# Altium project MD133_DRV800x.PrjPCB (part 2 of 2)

## Sheet MD133_TCAN284x.SchDoc: TCAN284x-Q1
size 431 x 279 mm; Date: Not shown in title block; ApprovedBy: Not shown in title block; CheckedBy: Not shown in title block; Author: Not shown in title block; CompanyName: Not shown in title block; DrawnBy: Mojtaba Afshar; Engineer: Not shown in title block; Organization: Not shown in title block; Address1: Not shown in title block; Address2: Not shown in title block; Address3: Not shown in title block; Address4: Not shown in title block; DocumentNumber: 1; Revision: Use project parameter SCH_Rev; SheetNumber: 5; SheetTotal: 1; PageSetup: Record=PageOptions¦CenterHorizontal=True¦CenterVertical=True¦PrintScale=1.00¦XCorrection=1.00¦YCorrection=1.00¦PrintKind=0¦BorderSize=5000000¦LeftOffset=0¦BottomOffset=0¦Orientation=2¦PaperLength=1000¦PaperWidth=1000¦Scale=100¦PaperSource=15¦PrintQuality=600¦MediaType=1¦DitherType=10¦PaperKind=Letter¦PrintScaleMode=1
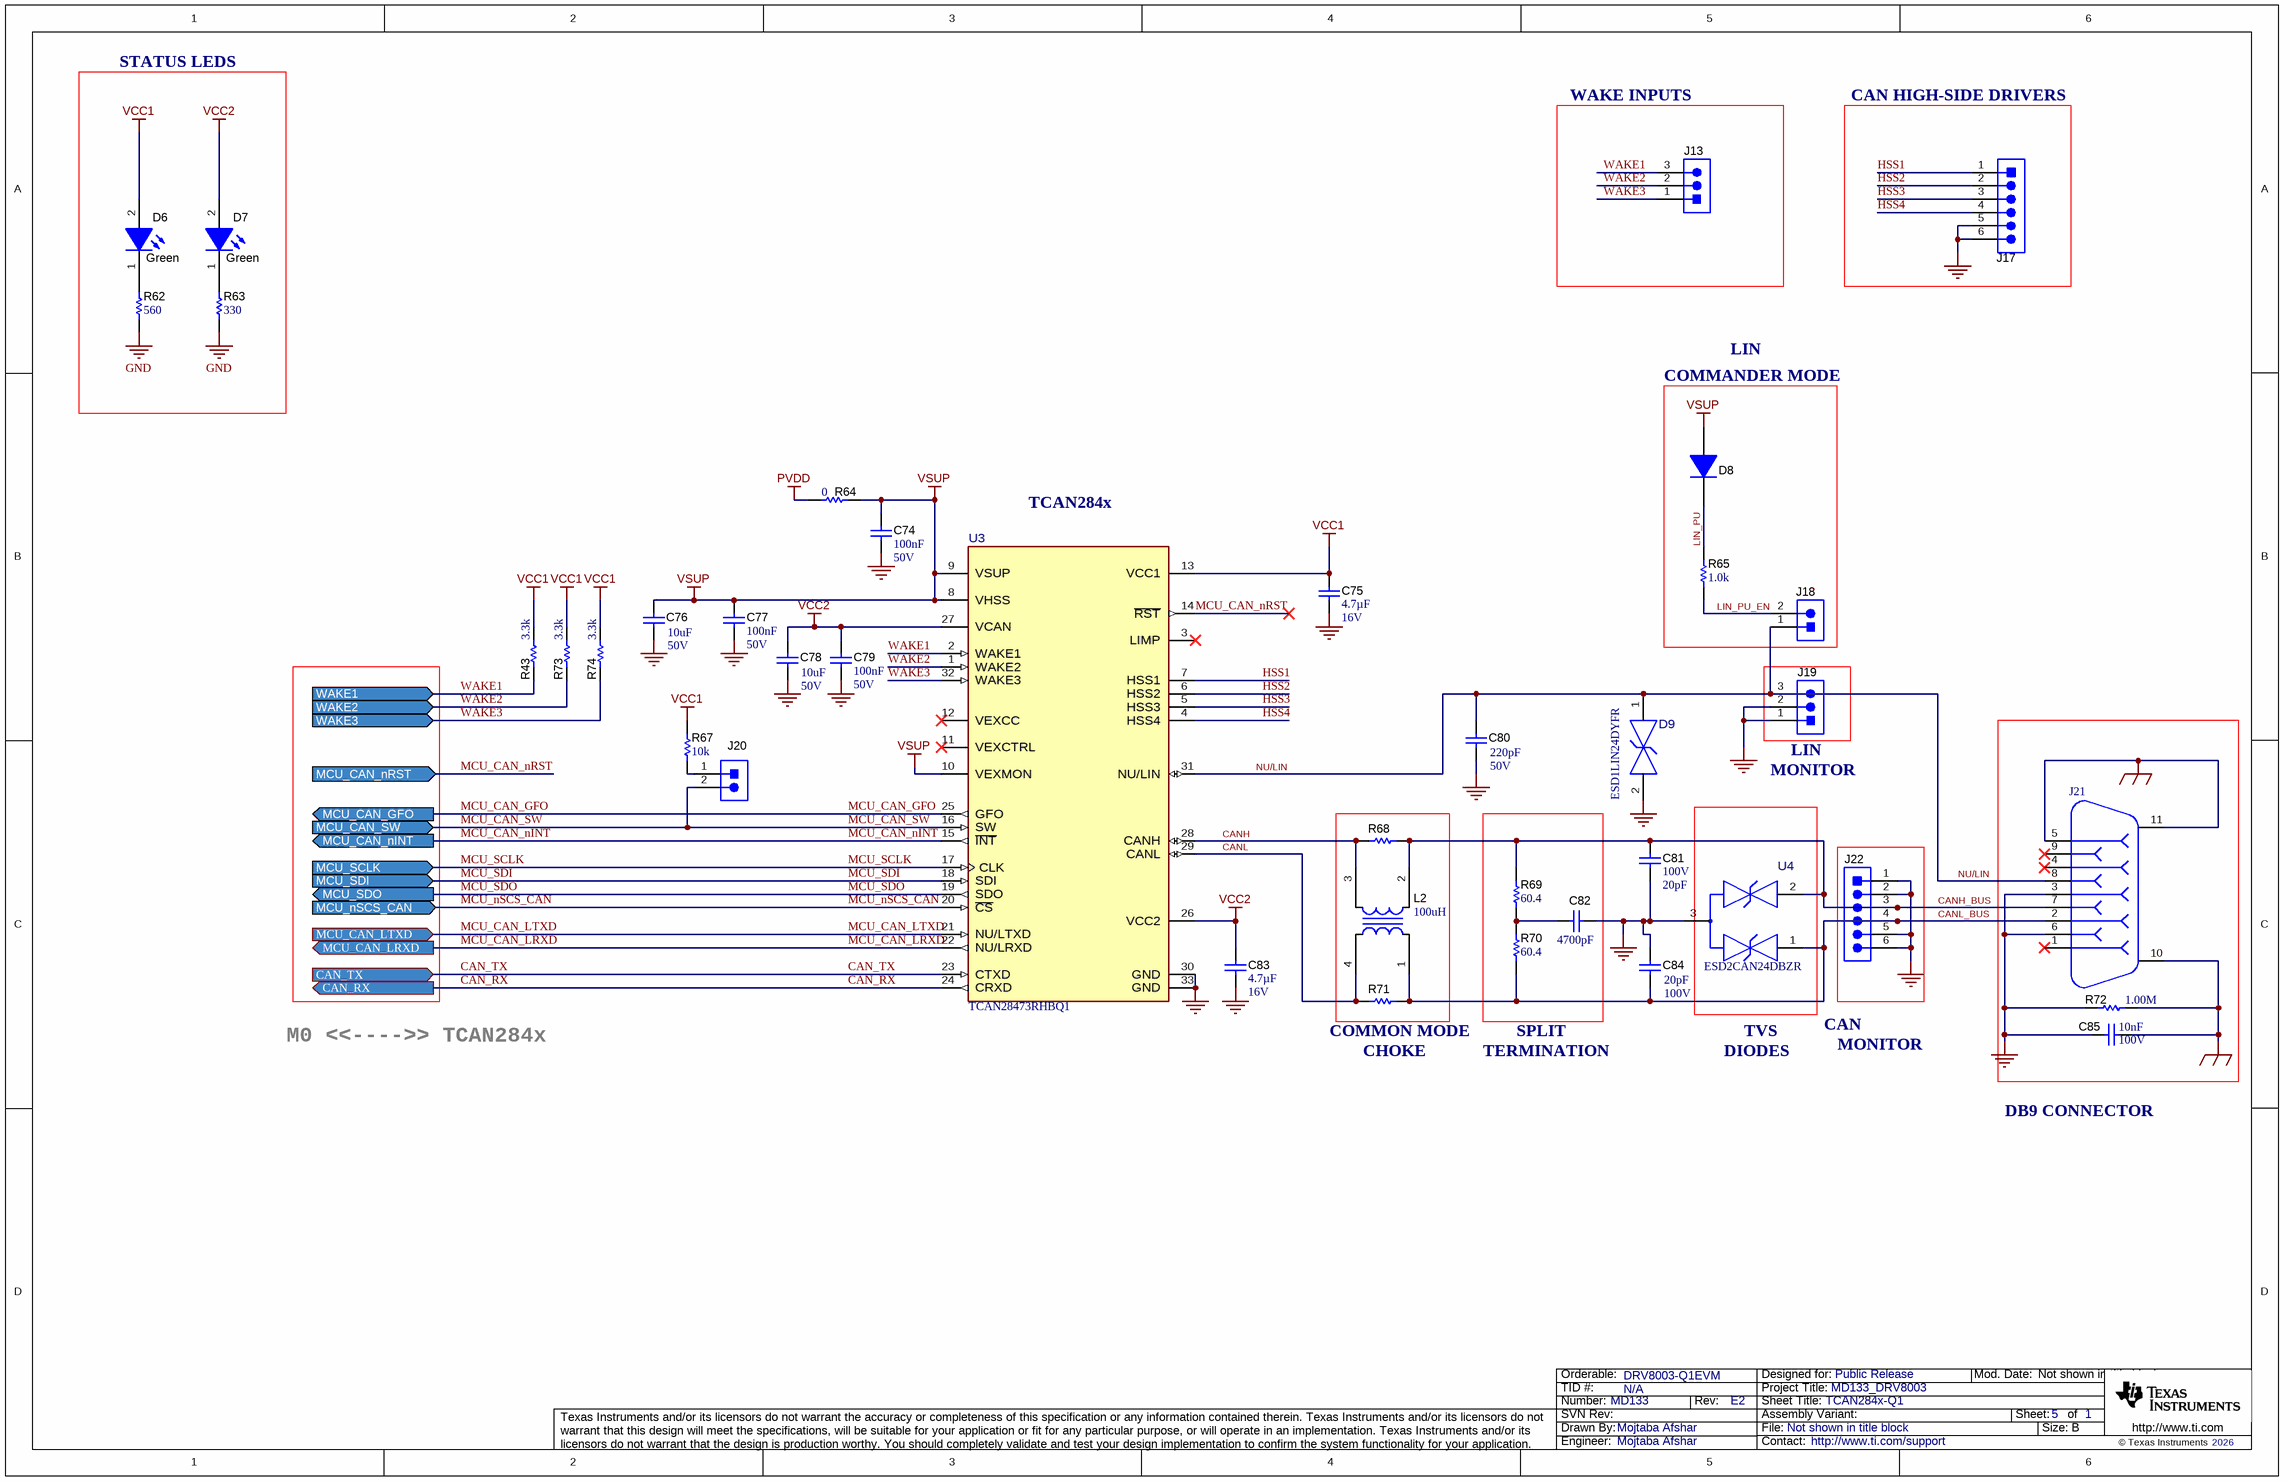
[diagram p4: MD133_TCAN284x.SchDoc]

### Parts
C74  Cap_F: 100nF  VDC_V: 50V  [0603S]  (hidden comment: C1608X7R1H104K080AA)
C75  Cap_F: 4.7µF  VDC_V: 16V  [0805L]  (hidden comment: CGA4J3X7R1C475K125AE)
C76  VDC_V: 50V  ValueDisplayed: 10uF  [1206_180]  (hidden comment: CL31B106KBHNNNE)
C77  Cap_F: 100nF  VDC_V: 50V  [0603S]  (hidden comment: C1608X7R1H104K080AA)
C78  VDC_V: 50V  ValueDisplayed: 10uF  [1206_180]  (hidden comment: CL31B106KBHNNNE)
C79  Cap_F: 100nF  VDC_V: 50V  [0603S]  (hidden comment: C1608X7R1H104K080AA)
C80  Value2: 50V  ValueDisplayed: 220pF  [0603S]  (hidden comment: 06035A221FAT2A)
C81  VDC_V: 100V  ValueDisplayed: 20pF  [0603S]  (hidden comment: GRM1885C2A200JA01D)
C82  ValueDisplayed: 4700pF  [0603S]  (hidden comment: 06031C472KAT2A)
C83  Cap_F: 4.7µF  VDC_V: 16V  [0805L]  (hidden comment: CGA4J3X7R1C475K125AE)
C84  VDC_V: 100V  ValueDisplayed: 20pF  [0603S]  (hidden comment: GRM1885C2A200JA01D)
C85  Cap_F: 10nF  VDC_V: 100V  [0603S]  (hidden comment: C0603X103K1RACTU)
D6  value Green  [WL-SMCW_GREEN]  (hidden comment: 150060VS75000)
D7  value Green  [WL-SMCW_GREEN]  (hidden comment: 150060VS75000)
D8  1N4148W-TP  [SOD-123]  (value not drawn)
D9  ESD1LIN24DYFR  [DYF0002A-MFG]
J13  TSW-103-07-G-S  [TSW-103-07-G-S]  (value not drawn)
J17  TSW-106-07-G-S  [TSW-106-07-G-S]  (value not drawn)
J18  TSW-102-07-G-S  [TSW-102-07-G-S]  (value not drawn)
J19  TSW-103-07-G-S  [TSW-103-07-G-S]  (value not drawn)
J20  TSW-102-07-G-S  [TSW-102-07-G-S]  (value not drawn)
J21  190-009-263R001  [NORCOMP_190-009-263R001]  (value not drawn)
J22  TSW-106-07-G-S  [TSW-106-07-G-S]  (value not drawn)
L2  ValueDisplayed: 100uH  [ACT45B_NoSilk]  (hidden comment: ACT45B-101-2P-TL003)
R43  ValueDisplayed: 3.3k  [0603]  (hidden comment: RC0603JR-073K3L)
R62  ValueDisplayed: 560  [0603]  (hidden comment: RC0603JR-07560RL)
R63  ValueDisplayed: 330  [0603]  (hidden comment: RC0603JR-07330RL)
R64  value 0  [0603]  (hidden comment: Resistor)
R65  ValueDisplayed: 1.0k  [0603]  (hidden comment: RC0603JR-071KL)
R67  ValueDisplayed: 10k  [0603]  (hidden comment: RC0603JR-0710KL)
R68  RC0603JR-070RL  [0603]  (value not drawn)
R69  ValueDisplayed: 60.4  [0603S]  (hidden comment: RC0603FR-0760R4L)
R70  ValueDisplayed: 60.4  [0603S]  (hidden comment: RC0603FR-0760R4L)
R71  RC0603JR-070RL  [0603]  (value not drawn)
R72  ValueDisplayed: 1.00M  [0402S]  (hidden comment: ERJ-2RKF1004X)
R73  ValueDisplayed: 3.3k  [0603]  (hidden comment: RC0603JR-073K3L)
R74  ValueDisplayed: 3.3k  [0603]  (hidden comment: RC0603JR-073K3L)
U3  TCAN28473RHBQ1  [RHB0032U-MFG]
U4  ESD2CAN24DBZR  [DBZ0003A-MFG]

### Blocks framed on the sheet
STATUS LEDS: D6 D7 R62 R63
WAKE INPUTS: J13
CAN HIGH-SIDE DRIVERS: J17
COMMANDER MODE: D8 J18 R65

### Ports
CAN_RX (out), CAN_TX (in), MCU_CAN_GFO (out), MCU_CAN_LRXD (out), MCU_CAN_LTXD (in), MCU_CAN_nINT (out), MCU_CAN_nRST (in), MCU_CAN_SW (in), MCU_nSCS_CAN (in), MCU_SCLK (in), MCU_SDI (in), MCU_SDO (out), WAKE1 (in), WAKE2 (in), WAKE3 (in)

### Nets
GND: C74.2 C75.2 C76.2 C77.2 C78.2 C79.2 C80.2 C81.2 C82.1 C83.2 C84.1 C85.2 D9.2(GND) J17.5 J17.6 J19.1 J19.2 J21.3 J21.6 J22.1 J22.2 J22.5 J22.6 R62.1 R63.1 R72.1 U3.30(GND) U3.33(GND) U4.3(GND)
PVDD: R64.2
SHIELD_GND: C85.1 J21.5 J21.10 J21.11 R72.2
VCC1: C75.1 D6.2(A) R43.2 R67.2 R73.2 R74.2 U3.13(VCC1)
VCC2: C78.1 C79.1 C83.1 D7.2(A) U3.26(VCC2) U3.27(VCAN)
VSUP: C74.1 C76.1 C77.1 D8.2(A) R64.1 U3.8(VHSS) U3.9(VSUP) U3.10(VEXMON)
CAN_RX: U3.24(CRXD) ; port CAN_RX
CAN_TX: U3.23(CTXD) ; port CAN_TX
CANH: L2.3 R68.1 U3.28(CANH)
CANH_BUS: C81.1 J21.7 J22.3 L2.2 R68.2 R69.2 U4.2(2_IO)
CANL: L2.4 R71.1 U3.29(CANL)
CANL_BUS: C84.2 J21.2 J22.4 L2.1 R70.1 R71.2 U4.1(1_IO)
HSS1: J17.1 U3.7(HSS1)
HSS2: J17.2 U3.6(HSS2)
HSS3: J17.3 U3.5(HSS3)
HSS4: J17.4 U3.4(HSS4)
LIN_PU: D8.1(K) R65.1
LIN_PU_EN: J18.2 R65.2
MCU_CAN_GFO: U3.25(GFO) ; port MCU_CAN_GFO
MCU_CAN_LRXD: U3.22(NU/LRXD) ; port MCU_CAN_LRXD
MCU_CAN_LTXD: U3.21(NU/LTXD) ; port MCU_CAN_LTXD
MCU_CAN_nINT: U3.15(~{INT}) ; port MCU_CAN_nINT
MCU_CAN_nRST: U3.14(~{RST}) ; port MCU_CAN_nRST
MCU_CAN_SW: J20.2 U3.16(SW) ; port MCU_CAN_SW
MCU_nSCS_CAN: U3.20(~{CS}) ; port MCU_nSCS_CAN
MCU_SCLK: U3.17(CLK) ; port MCU_SCLK
MCU_SDI: U3.18(SDI) ; port MCU_SDI
MCU_SDO: U3.19(SDO) ; port MCU_SDO
NU/LIN: C80.1 D9.1(IO) J18.1 J19.3 J21.8 U3.31(NU/LIN)
WAKE1: J13.3 R43.1 U3.2(WAKE1) ; port WAKE1
WAKE2: J13.2 R73.1 U3.1(WAKE2) ; port WAKE2
WAKE3: J13.1 R74.1 U3.32(WAKE3) ; port WAKE3
NetC82_2: C82.2 R69.1 R70.2
NetD6_1: D6.1(K) R62.2
NetD7_1: D7.1(K) R63.2
NetJ20_1: J20.1 R67.1

Not connected (* = marked no-connect by the designer): J21 1* 4* 9*; U3 3(LIMP)* 11(VEXCTRL)* 12(VEXCC)*

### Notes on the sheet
- LIN
- TCAN284x
- (near J19) LIN
- (near J19) MONITOR
- CAN
- M0 <<---->> TCAN284x
- (near R71) COMMON MODE
- (near R71) CHOKE
- TERMINATION
- SPLIT
- DIODES
- TVS
- MONITOR
- DB9 CONNECTOR

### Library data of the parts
C74 C77 C79 = CMP-0007044-5: CAP, CERM, 0.1 uF, 50 V, +/- 10%, X7R, 0603; Manufacturer: TDK; TaMin_C: -55°C; ESR_ohm: 29.6m; Polarized: N; SizeAreaWB_mm2: 4.68; Value1: 0.0296 ohm; U/M: EA; Value: 0.1uF; TaMax_C: 125°C; SizeZ_mm: 1; SizeX_mm: 1.6; SizeY_mm: 0.8; Cap_Case: 0603; SizeArea_mm2: 1.28; IRMS_A: 971.99mA; AEC Category: Q200
C75 C83 = CMP-0080701-1: CAP, CERM, 4.7 µF, 16 V,+/- 10%, X7R, AEC-Q200 Grade 1, 0805; Manufacturer: TDK; SizeAreaWB_mm2: 6.75; SizeArea_mm2: 2.5; AEC Qualified: Y; AEC Category: Q200; Value: 4.7uF; TaMax_C: 125°C; SizeZ_mm: 1.45; AEC Grade: 1; Polarized: N; TaMin_C: -55°C; SizeY_mm: 1.25; U/M: EA; SizeX_mm: 2; Cap_Case: 0805
C76 C78 = CMP-0008802-2: CAP, CERM, 10 uF, 50 V, +/- 10%, X7R, 1206; Manufacturer: Samsung; TaMin_C: -55°C; Polarized: N; SizeAreaWB_mm2: 10.92; Value1: Unknown; U/M: EA; Value: 10uF; TaMax_C: 125°C; SizeZ_mm: 1.8; SizeX_mm: 3.2; SizeY_mm: 1.6; Cap_Case: 1206; SizeArea_mm2: 5.12; Cap_F: 10µF; AEC Category: Q200
C80 = CMP-0006776-4: CAP, CERM, 220 pF, 50 V, +/- 1%, C0G/NP0, 0603; Manufacturer: AVX; TaMin_C: -55°C; ESR_ohm: 83m; Polarized: N; SizeAreaWB_mm2: 4.68; Value1: 0.083 ohm; U/M: EA; Value: 220pF; TaMax_C: 125°C; SizeZ_mm: 1; SizeX_mm: 1.6; SizeY_mm: 0.8; Cap_Case: 0603; SizeArea_mm2: 1.28; AEC Category: Q200
C81 C84 = CMP-0007253-4: CAP, CERM, 20 pF, 100 V, +/- 5%, C0G/NP0, 0603; Manufacturer: MuRata; TaMin_C: -55°C; Polarized: N; SizeAreaWB_mm2: 4.68; Value1: Unknown; U/M: EA; Value: 20pF; TaMax_C: 125°C; SizeZ_mm: 1; SizeX_mm: 1.6; SizeY_mm: 0.8; Cap_Case: 0603; SizeArea_mm2: 1.28; AEC Category: Q200
C82 = CMP-0006746-5: CAP, CERM, 4700 pF, 100 V, +/- 10%, X7R, 0603; Manufacturer: AVX; TaMin_C: -55°C; ESR_ohm: 0.136; Polarized: N; SizeAreaWB_mm2: 4.68; Value1: 0.136 ohm; U/M: EA; Value: 4700pF; TaMax_C: 125°C; SizeZ_mm: 1; SizeX_mm: 1.6; SizeY_mm: 0.8; Cap_Case: 0603; Value2: 100V; SizeArea_mm2: 1.28; Cap_F: 4.7nF; AEC Category: Q200
C85 = CMP-0006977-4: CAP, CERM, 0.01 uF, 100 V, +/- 10%, X7R, 0603; Manufacturer: Kemet; TaMin_C: -55°C; Polarized: N; SizeAreaWB_mm2: 4.68; Value1: Unknown; U/M: EA; Value: 0.01uF; TaMax_C: 125°C; SizeZ_mm: 1; SizeX_mm: 1.6; SizeY_mm: 0.8; Cap_Case: 0603; SizeArea_mm2: 1.28; AEC Category: Q200
D6 D7 = CMP-0002894-2: LED, Green, SMD; Manufacturer: Wurth Elektronik; Type: AlInGaP; Value2: 2V; Io_A: 20mA; Value1: W
D8 = CMP-0076974-2: Diode, Switching, 100 V, 0.15 A, SOD-123; Manufacturer: Micro Commercial Components; SizeAreaWB_mm2: 13.095; Vr_V: 100V; SizeArea_mm2: 6.545; TJmax_C: 150°C; AEC Category: Q101; Value: 100V; SizeZ_mm: 1.35; Green_REACh: Incomplete; Io_A: 150mA; Vf_V: 1.25V; SizeY_mm: 1.7; Green_Lifecycle: Not Set; Value1: 0.15A; SizeX_mm: 3.85
D9 = CMP-0098376-1: 24-V, 1-Channel ESD Protection Diode; Manufacturer: Texas Instruments; AEC Qualified: No; SizeZ_mm: 1mm; VRWM: 24V; Ipp: 16A; Ppk: 159.1W; Breakdown Voltage: 25.5V; Cap_F: 2.3pF; Clamping Voltage: 40V; Direction: Bidirectional; Number Of Channels: 1; Standoff Height: 0mm; TaMax_C: +150°C; TaMin_C: -55°C
J13 J19 = CMP-0075407-2: Header, 100mil, 3x1, Gold, TH; Manufacturer: Samtec; Pitch_mm: 2.54; Gender: Male; Cert_CSA: Y; Row_Count: 1; Cert_CULUS: N; Current_A: 6.3A; Green_Lifecycle: Active; Green_REACh: Passed; Voltage_V: 550V
J17 J22 = CMP-0075413-2: Header, 100mil, 6x1, Gold, TH; Manufacturer: Samtec; Pitch_mm: 2.54; Cert_VDE: N; Gender: Male; Cert_CSA: Y; Voltage_V: 550V; Green_REACh: Passed; Current_A: 6.3A; Green_Lifecycle: Active; Row_Count: 1
J18 J20 = CMP-0075405-3: Header, 100mil, 2x1, Gold, TH; Manufacturer: Samtec; Pitch_mm: 2.54; Gender: Male; Cert_CSA: Y; Row_Count: 1; Cert_CULUS: N; Current_A: 6.3A; Green_Lifecycle: Active; Green_REACh: Passed; Voltage_V: 550V
J21 = CMP-0074875-1: Receptacle, D-Sub, 9 Position, R/A, SMT; Manufacturer: NorComp; CNHeader: False; Green_Lifecycle: Not Set; Gender: Female; Green_REACh: Incomplete; Row_Count: 2; ContactFinish: Gold; CT: True
L2 = CMP-0062430-2: Inductor, Ferrite, 100 uH, 0.15 A, 2 ohm, SMD; Manufacturer: TDK; Isat: 0.15A @ % inductance drop; Green_Lifecycle: Active; SizeAreaWB_mm2: 23.1; DCR_ohm: 2; Green_REACh: Passed; Value1: 2 ohm; Value: 100uH; Imax_A: 150mA; SizeZ_mm: 3; SizeX_mm: 4.5; SizeY_mm: 3.2; Value2: 0.15A; SizeArea_mm2: 14.4; Ind_H: 100µH; AEC Category: Q200
R43 R73 R74 = CMP-0025918-5: RES, 3.3 k, 5%, 0.1 W, 0603; Manufacturer: Yageo; Power_W: 100mW; TempCo: 100 ppm/C; Value_Code: 3k30; Value: 3.3k; SizeX_mm: 1.6; SizeY_mm: 0.8; SizeZ_mm: 1; Value2: 0.1W; SizeArea_mm2: 1.28; AEC Qualified: N; VDC_V: 75V; AEC Category: Q200; EIA_Code: E24; SizeAreaWB_mm2: 4.68
R62 = CMP-0025930-5: RES, 560, 5%, 0.1 W, 0603; Manufacturer: Yageo; Power_W: 100mW; TempCo: 100 ppm/C; Value_Code: 560R; Value: 560; EIA_Code: E24; SizeX_mm: 1.6; SizeY_mm: 0.8; SizeZ_mm: 1; Value2: 0.1W; SizeArea_mm2: 1.28; AEC Qualified: N; VDC_V: 75V; AEC Category: Q200; SizeAreaWB_mm2: 4.68
R63 = CMP-0025912-5: RES, 330, 5%, 0.1 W, 0603; Manufacturer: Yageo; Power_W: 100mW; TempCo: 100 ppm/C; Value_Code: 330R; Value: 330; EIA_Code: E24; SizeX_mm: 1.6; SizeY_mm: 0.8; SizeZ_mm: 1; Value2: 0.1W; SizeArea_mm2: 1.28; AEC Qualified: N; VDC_V: 75V; AEC Category: Q200; SizeAreaWB_mm2: 4.68
R64 = CMP-0025885-5: RES, 0, 5%, 0.1 W, 0603; PartNumber: RC0603JR-070RL; Manufacturer: Yageo; Power_W: 100mW; VDC_V: 75V; AEC Qualified: N; SizeZ_mm: 1; AEC Category: Q200; EIA_Code: E24; SizeArea_mm2: 1.28; SizeAreaWB_mm2: 4.68; SizeX_mm: 1.6; SizeY_mm: 0.8; TempCo: 200 ppm/C; Value2: 0.1W; Value_Code: 0000
R65 = CMP-0025899-5: RES, 1.0 k, 5%, 0.1 W, 0603; Manufacturer: Yageo; Power_W: 100mW; TempCo: 100 ppm/C; Value_Code: 1k00; Value: 1.0k; EIA_Code: E24; Res_ohm: 1k; SizeX_mm: 1.6; SizeY_mm: 0.8; SizeZ_mm: 1; Value2: 0.1W; SizeArea_mm2: 1.28; AEC Qualified: N; VDC_V: 75V; AEC Category: Q200; SizeAreaWB_mm2: 4.68
R67 = CMP-0025886-5: RES, 10 k, 5%, 0.1 W, 0603; Manufacturer: Yageo; Value: 10k; SizeY_mm: 0.8; SizeArea_mm2: 1.28; EIA_Code: E24; Power_W: 100mW; SizeX_mm: 1.6; Value2: 0.1W; Value_Code: 10k0; VDC_V: 75V; SizeZ_mm: 1; AEC Qualified: N; AEC Category: Q200; TempCo: 100 ppm/C; SizeAreaWB_mm2: 4.68
R68 R71 = CMP-0025885-5: RES, 0, 5%, 0.1 W, 0603; Manufacturer: Yageo; AEC Qualified: N; Res_ohm: 0; Value: 0; SizeZ_mm: 1; Power_W: 100mW; VDC_V: 75V; AEC Category: Q200; EIA_Code: E24; SizeArea_mm2: 1.28; SizeAreaWB_mm2: 4.68; SizeX_mm: 1.6; SizeY_mm: 0.8; TempCo: 200 ppm/C; Value2: 0.1W; Value_Code: 0000
R69 R70 = CMP-0023213-5: RES, 60.4, 1%, 0.1 W, 0603; Manufacturer: Yageo; Power_W: 100mW; TempCo: 100 ppm/C; Value_Code: 60R4; Value: 60.4; EIA_Code: E96; SizeX_mm: 1.6; SizeY_mm: 0.8; SizeZ_mm: 1; Value2: 0.1W; SizeArea_mm2: 1.28; AEC Qualified: N; VDC_V: 75V; AEC Category: Q200; SizeAreaWB_mm2: 4.68
R72 = CMP-0026660-1: RES, 1.00 M, 1%, 0.1 W, 0402; Manufacturer: Panasonic; Power_W: 100mW; TempCo: 100 ppm/C; Value_Code: 1M00; U/M: EA; Value: 1.00Meg; EIA_Code: E96; Res_ohm: 1M; SizeX_mm: 1; SizeY_mm: 0.5; SizeZ_mm: 0.6; Value2: 0.1W; VDC_V: 50V; AEC Category: Q200
U3 = CMP-0093295-1: CAN FD and LIN System Basis Chip (SBC) with Integrated Watchdog, Selective Wake and Advanced CAN Bus Fault Diagnostics; Manufacturer: Texas Instruments; TJmax_C: +150°C; Min Supply Voltage: 4.5V; Interface: SPI,CAN,LIN; Standoff Height: 0mm; AEC Grade: Grade 1; SizeZ_mm: 1mm; Max Supply Voltage: 28V; AEC Qualified: Yes
U4 = CMP-0093261-1: 24-V, 2-Channel ESD Protection Diode for In-Vehicle Networks; Manufacturer: Texas Instruments; Cap_F: 3pF; Breakdown Voltage: 25.5V; Clamping Voltage: 32V; TaMax_C: +150°C; Direction: Bidirectional; TaMin_C: -55°C; Ipp: 3.5A; VRWM: 24V; Standoff Height: 0.01mm; SizeZ_mm: 1.12mm; Ppk: 147W; AEC Qualified: No; Number Of Channels: 2

## Sheet MD133_DRV800x.SchDoc: DRV800x-Q1
size 431 x 279 mm; VersionControl_RevNumber: 1; Date: Not shown in title block; ApprovedBy: Not shown in title block; CheckedBy: Not shown in title block; Author: Not shown in title block; CompanyName: Not shown in title block; DrawnBy: Mojtaba Afshar; Engineer: Not shown in title block; Organization: Not shown in title block; Address1: Not shown in title block; Address2: Not shown in title block; Address3: Not shown in title block; Address4: Not shown in title block; DocumentNumber: 1; Revision: 1; SheetNumber: 4; SheetTotal: 1; PageSetup: Record=PageOptions¦CenterHorizontal=True¦CenterVertical=True¦PrintScale=1.00¦XCorrection=1.00¦YCorrection=1.00¦PrintKind=0¦BorderSize=5000000¦LeftOffset=0¦BottomOffset=0¦Orientation=2¦PaperLength=1000¦PaperWidth=1000¦Scale=100¦PaperSource=15¦PrintQuality=600¦MediaType=1¦DitherType=10¦PaperKind=Letter¦PrintScaleMode=1; VersionControl_ProjFolderRevNumber: 1; VersionControl_RevNumberShort: 1; VersionControl_ProjFolderRevNumberShort: 1
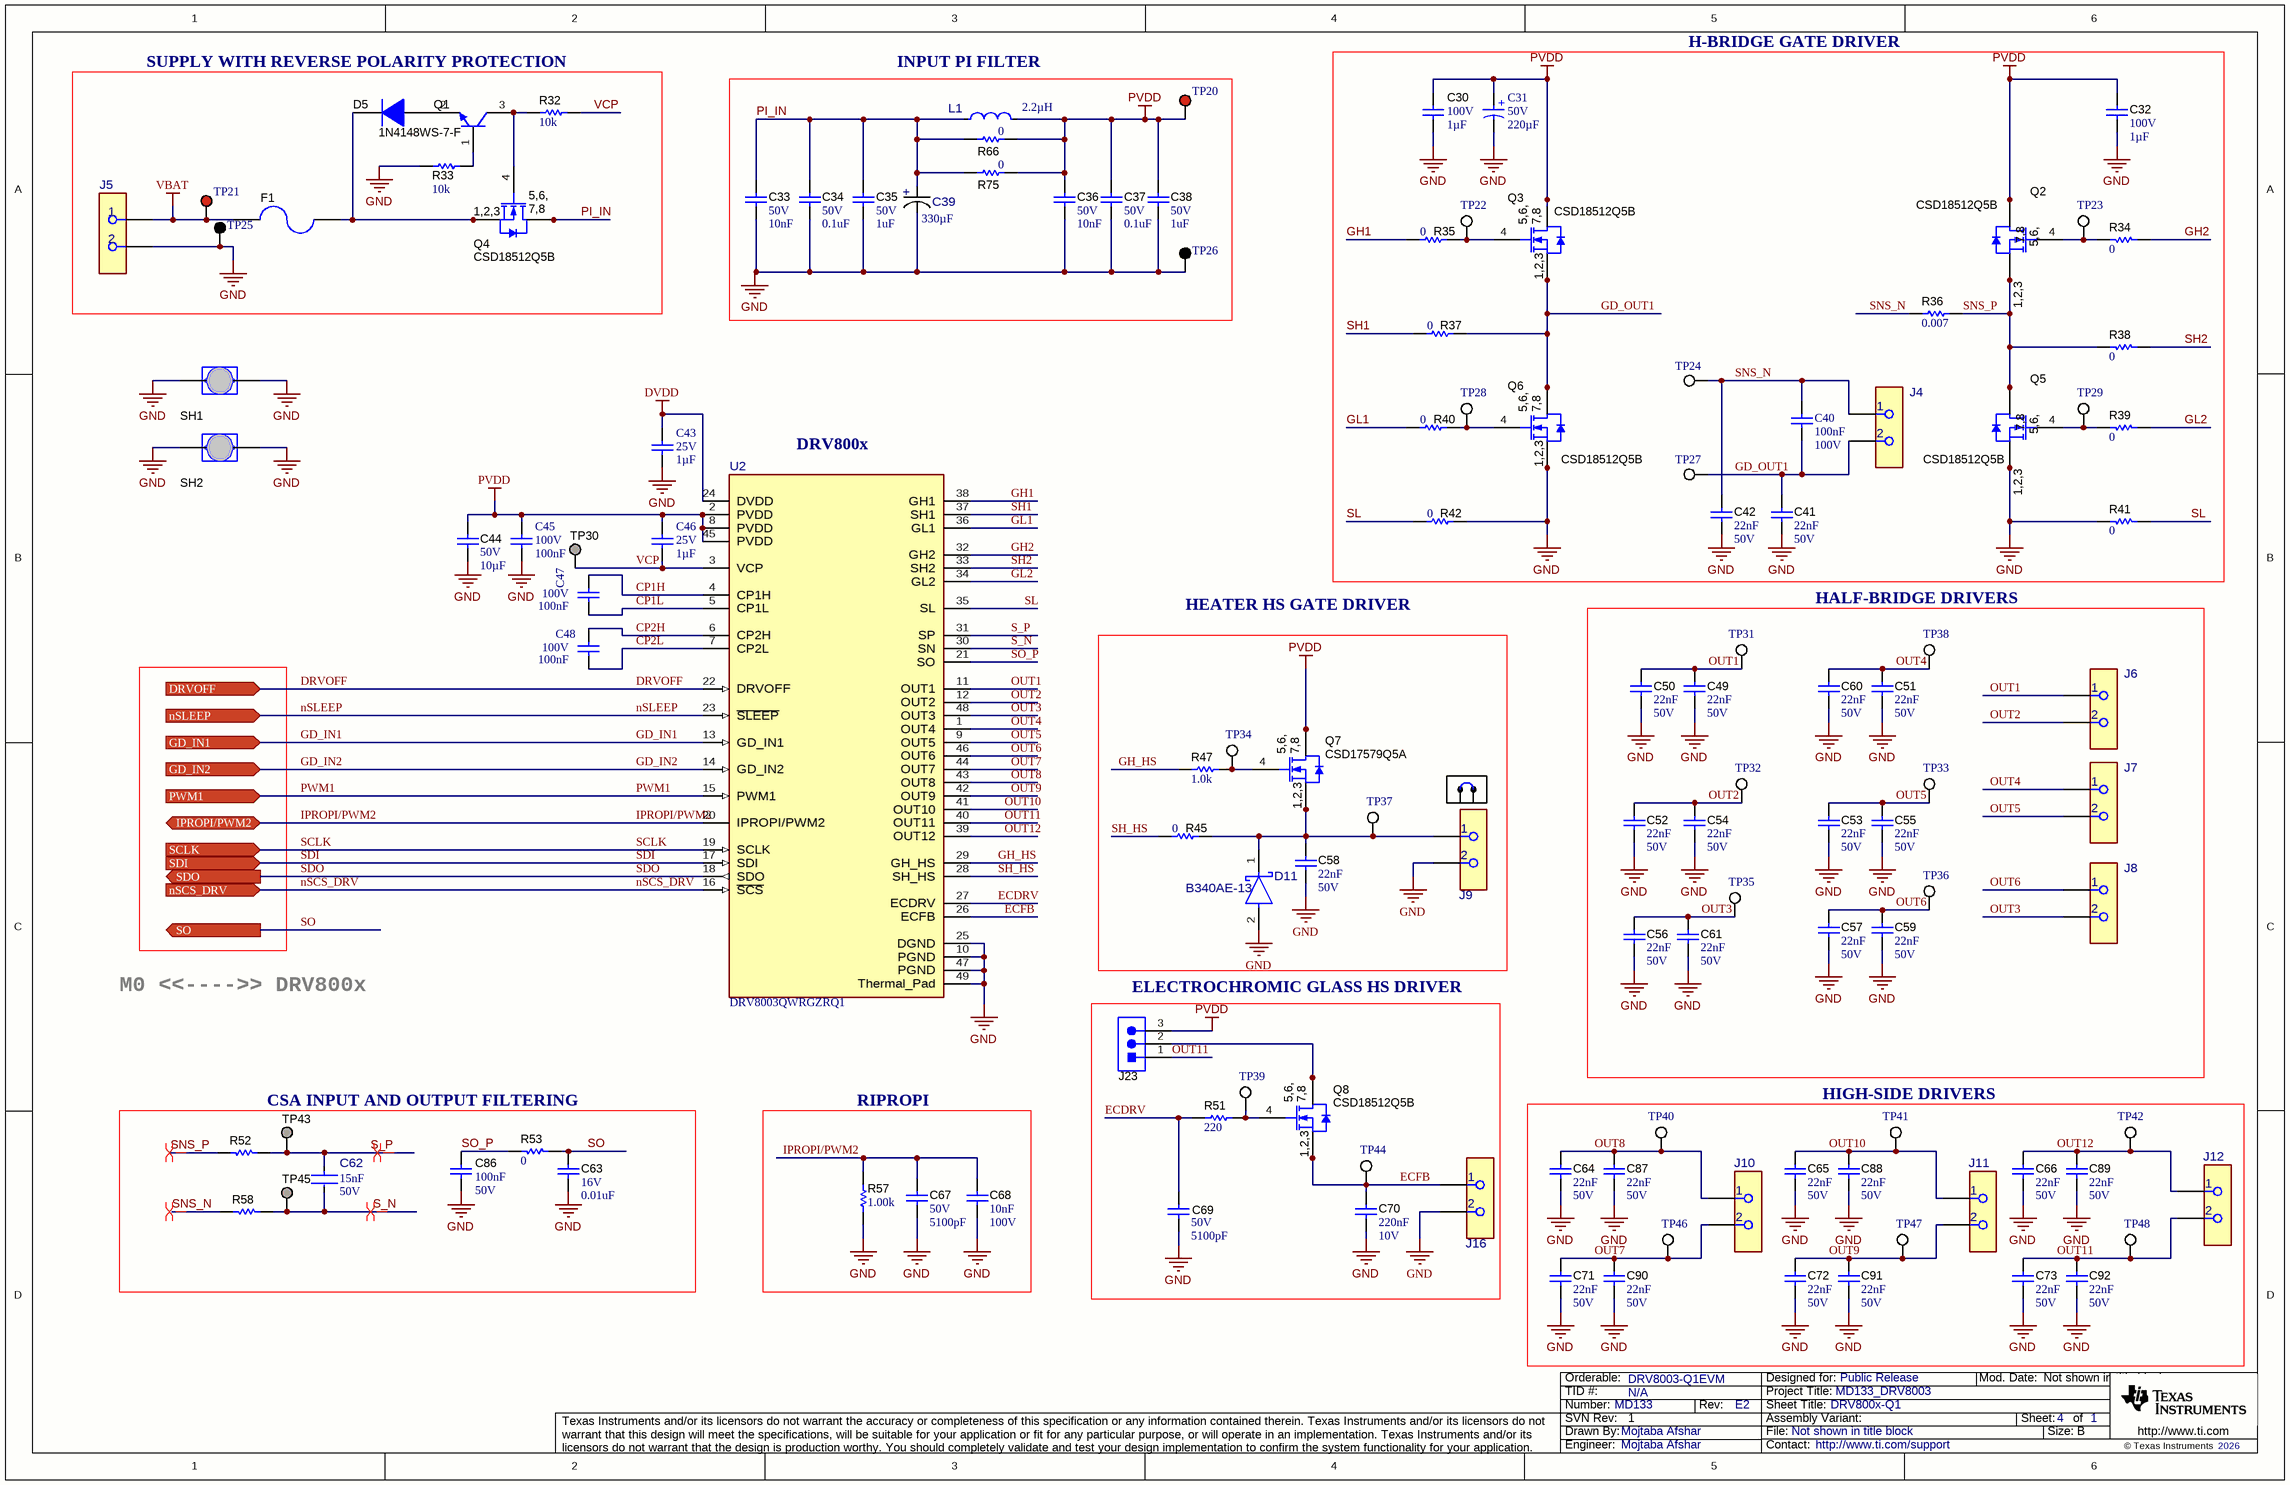
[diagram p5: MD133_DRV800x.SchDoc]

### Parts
C30  VDC_V: 100V  ValueDisplayed: 1µF  [1206_180]  (hidden comment: CC1206KKX7R0BB105)
C31  value 220µF  Rated Voltage (DC): 50V  [WCAP-ATG5_D10H12.5]  (hidden comment: 860020675020)
C32  VDC_V: 100V  ValueDisplayed: 1µF  [1206_180]  (hidden comment: CC1206KKX7R0BB105)
C33  VDC_V: 50V  Cap_F: 10nF  [0603L]  (hidden comment: 885012206089)
C34  VDC_V: 50V  ValueDisplayed: 0.1uF  [0603]  (hidden comment: 885012206095)
C35  VDC_V: 50V  ValueDisplayed: 1uF  [0805L]  (hidden comment: 885012207103)
C36  VDC_V: 50V  Cap_F: 10nF  [0603L]  (hidden comment: 885012206089)
C37  VDC_V: 50V  ValueDisplayed: 0.1uF  [0603]  (hidden comment: 885012206095)
C38  VDC_V: 50V  ValueDisplayed: 1uF  [0805L]  (hidden comment: 885012207103)
C39  Cap_F: 330µF  [FP-860020675021_RADIAL-MFG]  (hidden comment: 860020675021)
C40  Cap_F: 100nF  Rated Voltage (DC): 100V  [WCAP-CSGP_0603_L1.6W0.8H0.8_Reflow]  (hidden comment: 885012206120)
C41  Cap_F: 22nF  VDC_V: 50V  [0603]  (hidden comment: 885012206091)
C42  Cap_F: 22nF  VDC_V: 50V  [0603]  (hidden comment: 885012206091)
C43  value 1µF  Rated Voltage (DC): 25V  [WCAP-CSGP_0603_L1.6W0.8H0.8_Reflow]  (hidden comment: 885012206076)
C44  VDC_V: 50V  ValueDisplayed: 10µF  [1206_180]  (hidden comment: 885012108022)
C45  value 100nF  Rated Voltage (DC): 100V  [WCAP-CSGP_0603_L1.6W0.8H0.8_Reflow]  (hidden comment: 885012206120)
C46  value 1µF  Rated Voltage (DC): 25V  [WCAP-CSGP_0603_L1.6W0.8H0.8_Reflow]  (hidden comment: 885012206076)
C47  value 100nF  Rated Voltage (DC): 100V  [WCAP-CSGP_0603_L1.6W0.8H0.8_Reflow]  (hidden comment: 885012206120)
C48  value 100nF  Rated Voltage (DC): 100V  [WCAP-CSGP_0603_L1.6W0.8H0.8_Reflow]  (hidden comment: 885012206120)
C49  Cap_F: 22nF  VDC_V: 50V  [0603]  (hidden comment: 885012206091)
C50  Cap_F: 22nF  VDC_V: 50V  [0603]  (hidden comment: 885012206091)
C51  Cap_F: 22nF  VDC_V: 50V  [0603]  (hidden comment: 885012206091)
C52  Cap_F: 22nF  VDC_V: 50V  [0603]  (hidden comment: 885012206091)
C53  Cap_F: 22nF  VDC_V: 50V  [0603]  (hidden comment: 885012206091)
C54  Cap_F: 22nF  VDC_V: 50V  [0603]  (hidden comment: 885012206091)
C55  Cap_F: 22nF  VDC_V: 50V  [0603]  (hidden comment: 885012206091)
C56  Cap_F: 22nF  VDC_V: 50V  [0603]  (hidden comment: 885012206091)
C57  Cap_F: 22nF  VDC_V: 50V  [0603]  (hidden comment: 885012206091)
C58  Cap_F: 22nF  VDC_V: 50V  [0603]  (hidden comment: 885012206091)
C59  Cap_F: 22nF  VDC_V: 50V  [0603]  (hidden comment: 885012206091)
C60  Cap_F: 22nF  VDC_V: 50V  [0603]  (hidden comment: 885012206091)
C61  Cap_F: 22nF  VDC_V: 50V  [0603]  (hidden comment: 885012206091)
C62  Cap_F: 15nF  VDC_V: 50V  [FP-885012206090_0603-MFG]  (hidden comment: 885012206090)
C63  VDC_V: 16V  ValueDisplayed: 0.01uF  [0603L]  (hidden comment: 885012206040)
C64  Cap_F: 22nF  VDC_V: 50V  [0603]  (hidden comment: 885012206091)
C65  Cap_F: 22nF  VDC_V: 50V  [0603]  (hidden comment: 885012206091)
C66  Cap_F: 22nF  VDC_V: 50V  [0603]  (hidden comment: 885012206091)
C67  VDC_V: 50V  ValueDisplayed: 5100pF  [0603]  (hidden comment: C0603C512J5GAC7867)
C68  Cap_F: 10nF  VDC_V: 100V  [0603]  (hidden comment: 885012206114)
C69  VDC_V: 50V  ValueDisplayed: 5100pF  [0603]  (hidden comment: C0603C512J5GAC7867)
C70  Cap_F: 220nF  VDC_V: 10V  [0603]  (hidden comment: 885012206022)
C71  Cap_F: 22nF  VDC_V: 50V  [0603]  (hidden comment: 885012206091)
C72  Cap_F: 22nF  VDC_V: 50V  [0603]  (hidden comment: 885012206091)
C73  Cap_F: 22nF  VDC_V: 50V  [0603]  (hidden comment: 885012206091)
C86  Cap_F: 100nF  VDC_V: 50V  [0603]  (hidden comment: 885012206095)
C87  Cap_F: 22nF  VDC_V: 50V  [0603]  (hidden comment: 885012206091)
C88  Cap_F: 22nF  VDC_V: 50V  [0603]  (hidden comment: 885012206091)
C89  Cap_F: 22nF  VDC_V: 50V  [0603]  (hidden comment: 885012206091)
C90  Cap_F: 22nF  VDC_V: 50V  [0603]  (hidden comment: 885012206091)
C91  Cap_F: 22nF  VDC_V: 50V  [0603]  (hidden comment: 885012206091)
C92  Cap_F: 22nF  VDC_V: 50V  [0603]  (hidden comment: 885012206091)
D5  1N4148WS-7-F  [SOD-323]
D11  B340AE-13  [FP-B340AE-13_SMA-MFG]
F1  0463030.ER  [Fuse_0463]  (value not drawn)
J4  691250610002  [FP-691250610002_CONN_TERM_BLOCK2-MFG]  (value not drawn)
J5  691256610002  [FP-691256610002_HDR2-MFG]  (value not drawn)
J6  691250610002  [FP-691250610002_CONN_TERM_BLOCK2-MFG]  (value not drawn)
J7  691250610002  [FP-691250610002_CONN_TERM_BLOCK2-MFG]  (value not drawn)
J8  691250610002  [FP-691250610002_CONN_TERM_BLOCK2-MFG]  (value not drawn)
J9  691250610002  [FP-691250610002_CONN_TERM_BLOCK2-MFG]  (value not drawn)
J10  691216710002  [FP-691216710002_HDR2-MFG]  (value not drawn)
J11  691216710002  [FP-691216710002_HDR2-MFG]  (value not drawn)
J12  691216710002  [FP-691216710002_HDR2-MFG]  (value not drawn)
J16  691250610002  [FP-691250610002_CONN_TERM_BLOCK2-MFG]  (value not drawn)
J23  TSW-103-07-G-S  [TSW-103-07-G-S]  (value not drawn)
L1  Ind_H: 2.2µH  [FP-74439369022_IND_SMT_11MM6_10MM5-MFG]  (hidden comment: 74439369022)
Q1  BC846BLT1G  [SOT-23L]  (value not drawn)
Q2  CSD18512Q5B  [DNK0008A]
Q3  CSD18512Q5B  [DNK0008A]
Q4  CSD18512Q5B  [DNK0008A]
Q5  CSD18512Q5B  [DNK0008A]
Q6  CSD18512Q5B  [DNK0008A]
Q7  CSD17579Q5A  [DQJ0008A]
Q8  CSD18512Q5B  [DNK0008A]
R32  ValueDisplayed: 10k  [0603]  (hidden comment: RC0603JR-0710KL)
R33  ValueDisplayed: 10k  [0603]  (hidden comment: RC0603JR-0710KL)
R34  value 0  [0603]  (hidden comment: Resistor)
R35  value 0  [0603]  (hidden comment: Resistor)
R36  ValueDisplayed: 0.007  [WSHM2818]  (hidden comment: WSHM28187L000FEA)
R37  value 0  [0603]  (hidden comment: Resistor)
R38  value 0  [0603]  (hidden comment: Resistor)
R39  value 0  [0603]  (hidden comment: Resistor)
R40  value 0  [0603]  (hidden comment: Resistor)
R41  value 0  [0603]  (hidden comment: Resistor)
R42  value 0  [0603]  (hidden comment: Resistor)
R45  value 0  [0603]  (hidden comment: Resistor)
R47  ValueDisplayed: 1.0k  [0603]  (hidden comment: RC0603JR-071KL)
R51  ValueDisplayed: 220  [0603]  (hidden comment: RC0603FR-07220RL)
R52  RC0603JR-070RL  [0603]  (value not drawn)
R53  value 0  [0603]  (hidden comment: Resistor)
R57  ValueDisplayed: 1.00k  [0603]  (hidden comment: RC0603FR-071KL)
R58  RC0603JR-070RL  [0603]  (value not drawn)
R66  ValueDisplayed: 0  [2512_084]  (hidden comment: HCJ2512ZT0R00)
R75  ValueDisplayed: 0  [2512_084]  (hidden comment: HCJ2512ZT0R00)
SH1  Jumper_2p  [Harwin_D3082-05]  (value not drawn)
SH2  Jumper_2p  [Harwin_D3082-05]  (value not drawn)
SH-J21  60900213421  [Wurth_60900213421]  (value not drawn)
TP20  5010  [Keystone5010]  (value not drawn)
TP21  5010  [Keystone5010]  (value not drawn)
TP22  5012  [Keystone5012]  (value not drawn)
TP23  5012  [Keystone5012]  (value not drawn)
TP24  5012  [Keystone5012]  (value not drawn)
TP25  5011  [Keystone5011]  (value not drawn)
TP26  5011  [Keystone5011]  (value not drawn)
TP27  5012  [Keystone5012]  (value not drawn)
TP28  5012  [Keystone5012]  (value not drawn)
TP29  5012  [Keystone5012]  (value not drawn)
TP30  TP_H0.45P0.75  [TP_H045P075]  (value not drawn)  (no BOM)
TP31  5012  [Keystone5012]  (value not drawn)
TP32  5012  [Keystone5012]  (value not drawn)
TP33  5012  [Keystone5012]  (value not drawn)
TP34  5012  [Keystone5012]  (value not drawn)
TP35  5012  [Keystone5012]  (value not drawn)
TP36  5012  [Keystone5012]  (value not drawn)
TP37  5012  [Keystone5012]  (value not drawn)
TP38  5012  [Keystone5012]  (value not drawn)
TP39  5012  [Keystone5012]  (value not drawn)
TP40  5012  [Keystone5012]  (value not drawn)
TP41  5012  [Keystone5012]  (value not drawn)
TP42  5012  [Keystone5012]  (value not drawn)
TP43  TP_H0.45P0.75  [TP_H045P075]  (value not drawn)  (no BOM)
TP44  5012  [Keystone5012]  (value not drawn)
TP45  TP_H0.45P0.75  [TP_H045P075]  (value not drawn)  (no BOM)
TP46  5012  [Keystone5012]  (value not drawn)
TP47  5012  [Keystone5012]  (value not drawn)
TP48  5012  [Keystone5012]  (value not drawn)
U2  DRV8003QWRGZRQ1  [RGZ0048M-MFG]

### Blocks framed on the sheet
H-BRIDGE GATE DRIVER: C30-C32 C40-C42 J4 Q2 Q3 Q5 Q6 R34-R42 TP22-TP24 TP27-TP29
SUPPLY WITH REVERSE POLARITY PROTECTION: D5 F1 J5 Q1 Q4 R32 R33 TP21 TP25
INPUT PI FILTER: C33-C39 L1 R66 R75 TP20 TP26
HALF-BRIDGE DRIVERS: C49-C57 C59-C61 J6-J8 TP31-TP33 TP35 TP36 TP38
ELECTROCHROMIC GLASS HS DRIVER: C69 C70 J16 J23 Q8 R51 TP39 TP44
CSA INPUT AND OUTPUT FILTERING: C62 C63 C86 R52 R53 R58 TP43 TP45
RIPROPI: C67 C68 R57
HIGH-SIDE DRIVERS: C64-C66 C71-C73 C87-C92 J10-J12 TP40-TP42 TP46-TP48

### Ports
DRVOFF (in), GD_IN1 (in), GD_IN2 (in), IPROPI/PWM2 (bidir), nSCS_DRV (in), nSLEEP (in), PWM1 (in), SCLK (in), SDI (in), SDO (out), SO (out)

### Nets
DVDD: C43.2 U2.24(DVDD)
GND: C30.1 C31.2(N) C32.1 C33.2 C34.2 C35.2 C36.2 C37.2 C38.2 C39.1(CATHODE) C41.1 C42.1 C43.1 C44.2 C45.1 C49.1 C50.1 C51.1 C52.1 C53.1 C54.1 C55.1 C56.1 C57.1 C58.1 C59.1 C60.1 C61.1 C63.2 C64.1 C65.1 C66.1 C67.2 C68.2 C69.2 C70.2 C71.1 C72.1 C73.1 C86.2 C87.1 C88.1 C89.1 C90.1 C91.1 C92.1 D11.2(ANODE) J5.2 J9.2 J16.2 Q5.1(S) Q5.2(S) Q5.3(S) Q6.1(S) Q6.2(S) Q6.3(S) R33.1 R41.1 R42.1 R57.1 SH1.1 SH1.2 SH2.1 SH2.2 TP25.1 TP26.1 U2.10(PGND) U2.25(DGND) U2.47(PGND) U2.49(Thermal_Pad)
PVDD: C30.2 C31.1(P) C32.2 C36.1 C37.1 C38.1 C44.1 C45.2 C46.2 J23.3 L1.2 Q2.5(D) Q2.6(D) Q2.7(D) Q2.8(D) Q2.9(D) Q3.5(D) Q3.6(D) Q3.7(D) Q3.8(D) Q3.9(D) Q7.5(D) Q7.6(D) Q7.7(D) Q7.8(D) Q7.9(D) R66.2 R75.2 TP20.1 U2.2(PVDD) U2.8(PVDD) U2.45(PVDD)
VBAT: F1.2 J5.1 TP21.1
CP1H: C47.2 U2.4(CP1H)
CP1L: C47.1 U2.5(CP1L)
CP2H: C48.2 U2.6(CP2H)
CP2L: C48.1 U2.7(CP2L)
DRVOFF: U2.22(DRVOFF) ; port DRVOFF
ECDRV: C69.1 R51.1 U2.27(ECDRV)
ECFB: C70.1 J16.1 Q8.1(S) Q8.2(S) Q8.3(S) TP44.1 U2.26(ECFB)
GD_IN1: U2.13(GD_IN1) ; port GD_IN1
GD_IN2: U2.14(GD_IN2) ; port GD_IN2
GD_OUT1: C40.2 C41.2 J4.2 Q3.1(S) Q3.2(S) Q3.3(S) Q6.5(D) Q6.6(D) Q6.7(D) Q6.8(D) Q6.9(D) R37.1 TP27.1
GH1: R35.2 U2.38(GH1)
GH2: R34.2 U2.32(GH2)
GH_HS: R47.2 U2.29(GH_HS)
GL1: R40.2 U2.36(GL1)
GL2: R39.2 U2.34(GL2)
IPROPI/PWM2: C67.1 C68.1 R57.2 U2.20(IPROPI/PWM2) ; port IPROPI/PWM2
nSCS_DRV: U2.16(~{SCS}) ; port nSCS_DRV
nSLEEP: U2.23(~{SLEEP}) ; port nSLEEP
OUT1: C49.2 C50.2 J6.1 TP31.1 U2.11(OUT1)
OUT2: C52.2 C54.2 J6.2 TP32.1 U2.12(OUT2)
OUT3: C56.2 C61.2 J8.2 TP35.1 U2.48(OUT3)
OUT4: C51.2 C60.2 J7.1 TP38.1 U2.1(OUT4)
OUT5: C53.2 C55.2 J7.2 TP33.1 U2.9(OUT5)
OUT6: C57.2 C59.2 J8.1 TP36.1 U2.46(OUT6)
OUT7: C71.2 C90.2 J10.2 TP46.1 U2.44(OUT7)
OUT8: C64.2 C87.2 J10.1 TP40.1 U2.43(OUT8)
OUT9: C72.2 C91.2 J11.2 TP47.1 U2.42(OUT9)
OUT10: C65.2 C88.2 J11.1 TP41.1 U2.41(OUT10)
OUT11: C73.2 C92.2 J12.2 J23.1 TP48.1 U2.40(OUT11)
OUT12: C66.2 C89.2 J12.1 TP42.1 U2.39(OUT12)
PI_IN: C33.1 C34.1 C35.1 C39.2(ANODE) L1.1 Q4.5(D) Q4.6(D) Q4.7(D) Q4.8(D) Q4.9(D) R66.1 R75.1
PWM1: U2.15(PWM1) ; port PWM1
S_N: C62.2 R58.1 TP45.1 U2.30(SN)
S_P: C62.1 R52.1 TP43.1 U2.31(SP)
SCLK: U2.19(SCLK) ; port SCLK
SDI: U2.17(SDI) ; port SDI
SDO: U2.18(SDO) ; port SDO
SH1: R37.2 U2.37(SH1)
SH2: R38.2 U2.33(SH2)
SH_HS: R45.2 U2.28(SH_HS)
SL: R41.2 R42.2 U2.35(SL)
SNS_N: C40.1 C42.2 J4.1 R36.1 R58.2 TP24.1
SNS_P: Q2.1(S) Q2.2(S) Q2.3(S) Q5.5(D) Q5.6(D) Q5.7(D) Q5.8(D) Q5.9(D) R36.2 R38.1 R52.2
SO: C63.1 R53.1 ; port SO
SO_P: C86.1 R53.2 U2.21(SO)
VCP: C46.1 R32.1 TP30.1 U2.3(VCP)
NetC58_2: C58.2 D11.1(CATHODE) J9.1 Q7.1(S) Q7.2(S) Q7.3(S) R45.1 TP37.1
NetD5_1: D5.1(K) F1.1 Q4.1(S) Q4.2(S) Q4.3(S)
NetD5_2: D5.2(A) Q1.2(E)
NetJ23_2: J23.2 Q8.5(D) Q8.6(D) Q8.7(D) Q8.8(D) Q8.9(D)
NetQ1_1: Q1.1(B) R33.2
NetQ1_3: Q1.3(C) Q4.4(G) R32.2
NetQ2_4: Q2.4(G) R34.1 TP23.1
NetQ3_4: Q3.4(G) R35.1 TP22.1
NetQ5_4: Q5.4(G) R39.1 TP29.1
NetQ6_4: Q6.4(G) R40.1 TP28.1
NetQ7_4: Q7.4(G) R47.1 TP34.1
NetQ8_4: Q8.4(G) R51.2 TP39.1

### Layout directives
differential pair: S_N, S_P, SNS_N, SNS_P

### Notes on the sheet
- (near U2) DRV800x
- HEATER HS GATE DRIVER
- M0 <<---->> DRV800x

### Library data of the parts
C30 C32 = CMP-0077698-1: CAP, CERM, 1 µF, 100 V,+/- 10%, X7R, 1206; Manufacturer: Yageo America; TaMin_C: -55°C; Polarized: N; SizeAreaWB_mm2: 10.92; U/M: EA; Value: 1uF; TaMax_C: 125°C; SizeZ_mm: 1.8; SizeX_mm: 3.2; SizeY_mm: 1.6; Cap_Case: 1206; SizeArea_mm2: 5.12; AEC Category: Q200
C31 = CMP-0105981-1: WCAP-ATG5 Aluminum Electrolytic Capacitor, Radial, THT, D10 x H12.5mm, 220µF, 50V; Manufacturer: Wurth Elektronik; Capacitance Tolerance: +/-20%; Dissipation Factor: 10%; Endurance: 2000h; Leakage Current: 110uA; Ripple Current: 345mA; Technical Reference: ATDF125221M050DSPA9B000
C33 C36 = CMP-0750039-1: CAP, CERM, 0.01 µF, 50 V,+/- 10%, X7R, 0603; Manufacturer: Wurth Elektronik; Polarized: N; AEC Category: Q200; TaMax_C: 125°C; SizeAreaWB_mm2: 4.68; Value: 0.01uF; SizeArea_mm2: 1.28; SizeY_mm: 0.8; SizeZ_mm: 1; ValueDisplayed: 0.01µF; SizeX_mm: 1.6; U/M: EA; Cap_Case: 0603; TaMin_C: -55°C
C34 C37 = CMP-0006837-4: CAP, CERM, 0.1 uF, 50 V, +/- 10%, X7R, 0603; Manufacturer: Wurth Elektronik; TaMin_C: -55°C; Polarized: N; SizeAreaWB_mm2: 4.68; Value1: Unknown; U/M: EA; Value: 0.1uF; TaMax_C: 125°C; SizeZ_mm: 1; SizeX_mm: 1.6; SizeY_mm: 0.8; SizeArea_mm2: 1.28; Cap_F: 100nF; AEC Category: Q200
C35 C38 = CMP-0007696-2: CAP, CERM, 1 uF, 50 V, +/- 10%, X7R, 0805; Manufacturer: Wurth Elektronik; TaMin_C: -55°C; Polarized: N; SizeAreaWB_mm2: 6.75; Value1: Unknown; U/M: EA; Value: 1uF; TaMax_C: 125°C; SizeZ_mm: 1.45; SizeX_mm: 2; SizeY_mm: 1.25; Cap_Case: 0805; SizeArea_mm2: 2.5; Cap_F: 1µF; AEC Category: Q200
C39 = CMP-0087013-2: Electrolytic Capacitor, 330 uF, 50 V, WCAP-ATG5 Series, 20%, Radial Leaded, 10 mm; Manufacturer: Wurth Electronics; SizeZ_mm: 17.5mm; AEC Qualified: No; IRMS_A: 450mA; ValueDisplayed: 330uF
C40 C45 C47 C48 = CMP-0108322-1: WCAP-CSGP Multilayer Ceramic Chip Capacitor, General Purpose, size 0603, X7R, 100nF, 100VDC; Manufacturer: Wurth Elektronik; Capacitance Tolerance: +/-10%; Case/Size Code: 0603; Dissipation Factor: 5%; Insulation Resistance: 1GOhm; Technical Reference: X7R0603104K100DFCT10000
C41 C42 C49-C61 C64-C66 C71-C73 C87-C92 = CMP-0006836-4: CAP, CERM, 0.022 uF, 50 V, +/- 10%, X7R, 0603; Manufacturer: Wurth Elektronik; TaMin_C: -55°C; Polarized: N; SizeAreaWB_mm2: 4.68; Value1: Unknown; U/M: EA; TaMax_C: 125°C; SizeZ_mm: 1; SizeX_mm: 1.6; SizeY_mm: 0.8; SizeArea_mm2: 1.28; AEC Category: Q200
C43 C46 = CMP-0108290-1: WCAP-CSGP Multilayer Ceramic Chip Capacitor, General Purpose, size 0603, X7R, 1µF, 25VDC; Manufacturer: Wurth Elektronik; Capacitance Tolerance: +/-10%; Case/Size Code: 0603; Dissipation Factor: 10%; Insulation Resistance: 0.5GOhm; Technical Reference: X7R0603105K025DFCT10000
C44 = CMP-0081454-1: CAP, CERM, 10 µF, 50 V,+/- 20%, X5R, 1206; Manufacturer: Wurth Elektronik; TaMin_C: -55°C; Polarized: N; SizeAreaWB_mm2: 10.92; U/M: EA; Value: 10uF; TaMax_C: 125°C; SizeZ_mm: 1.8; SizeX_mm: 3.2; SizeY_mm: 1.6; Cap_Case: 1206; SizeArea_mm2: 5.12; AEC Category: Q200
C62 = CMP-0087155-1: CAP CER 0.015UF 50V X7R 0603; Manufacturer: Wurth Electronics; TempCo: 15%; SizeZ_mm: 0.95mm; Tolerance_%: 10%; AEC Qualified: No; Symbol Name: SYM-885012206090
C63 = CMP-0006828-4: CAP, CERM, 0.01 uF, 16 V, +/- 10%, X7R, 0603; Manufacturer: Wurth Elektronik; TaMin_C: -55°C; Polarized: N; SizeAreaWB_mm2: 4.68; Value1: Unknown; U/M: EA; Value: 0.01uF; TaMax_C: 125°C; SizeZ_mm: 1; SizeX_mm: 1.6; SizeY_mm: 0.8; Cap_Case: 0603; SizeArea_mm2: 1.28; Cap_F: 10nF; AEC Category: Q200
C67 C69 = CMP-0080094-1: CAP, CERM, 5100 pF, 50 V,+/- 5%, C0G/NP0, 0603; Manufacturer: Kemet; Cap_F: 5.1nF; SizeAreaWB_mm2: 4.68; SizeArea_mm2: 1.28; AEC Qualified: N; AEC Category: Q200; Value: 5100pF; TaMax_C: 125°C; SizeZ_mm: 1; Green_REACh: Passed; TaMin_C: -55°C; SizeY_mm: 0.8; Green_Lifecycle: Active; U/M: EA; SizeX_mm: 1.6
C68 = CMP-0079993-1: CAP, CERM, 0.01 µF, 100 V,+/- 10%, X7R, 0603; Manufacturer: Wurth Elektronik; TaMin_C: -55°C; Polarized: N; SizeAreaWB_mm2: 4.68; U/M: EA; Value: 0.01uF; TaMax_C: 105°C; SizeZ_mm: 1; SizeX_mm: 1.6; SizeY_mm: 0.8; SizeArea_mm2: 1.28; AEC Category: Q200; ValueDisplayed: 0.01µF
C70 = CMP-0074687-3: CAP, CERM, 0.22 µF, 10 V,+/- 10%, X7R, 0603; Manufacturer: Wurth Elektronik; TaMin_C: -55°C; Polarized: N; SizeAreaWB_mm2: 4.68; U/M: EA; Value: 0.22uF; TaMax_C: 125°C; SizeZ_mm: 1.0; SizeX_mm: 1.6; SizeY_mm: 0.8; SizeArea_mm2: 1.28; AEC Category: Q200; ValueDisplayed: 0.22µF
C86 = CMP-0006837-4: CAP, CERM, 0.1 uF, 50 V, +/- 10%, X7R, 0603; Manufacturer: Wurth Elektronik; TaMin_C: -55°C; Polarized: N; SizeAreaWB_mm2: 4.68; Value1: Unknown; U/M: EA; Value: 0.1uF; TaMax_C: 125°C; SizeZ_mm: 1; SizeX_mm: 1.6; SizeY_mm: 0.8; SizeArea_mm2: 1.28; AEC Category: Q200
D5 = CMP-0079597-2: Diode, Switching, 75 V, 0.15 A, AEC-Q101, SOD-323; Manufacturer: Diodes Inc.; Value: 75V; Vf_V: 1.25V; Value1: 0.15A; Io_A: 150mA; TJmax_C: 150°C; AEC Category: Q101; AEC Qualified: Y; SizeArea_mm2: 3.645; SizeAreaWB_mm2: 8.695; SizeX_mm: 2.7; SizeY_mm: 1.35; SizeZ_mm: 1
D11 = CMP-0128434-1: Rectifier Diode, Schottky, 1 Phase, 1 Element, 3A, 40V V(RRM), Silicon, DO-214AC; Manufacturer: Diodes Incorporated; AEC Qualified: No; SizeZ_mm: 2.4mm; TJmax_C: 150°C; Cap_F: 140pF; Max Surge Forward Current: 80A; Peak Reverse Current: 0.2mA; Standoff Height: 0.05mm
F1 = CMP-0077200-3: Fuse, 30 A, 250 VAC, 100 VDC, SMD; Manufacturer: Littelfuse; VAC_V: 250V; SizeAreaWB_mm2: 61.952; Rtyp_Ohm: 1.93m; SizeArea_mm2: 31.512; MeltingTyp: 916; Irating_A: 30A; SizeZ_mm: 3.12; VDC_V: 100V; SizeX_mm: 10.1; Interrupt_AC: 100A; Interrupt_DC: 50A; Fuse Speed: Fast; Fuse Technology: Board Mount; TaMax_C: 125°C; TaMin_C: -55°C
J4 J6-J9 J16 = CMP-0093233-2: 2 Position Wire to Board Terminal Block Horizontal with Board 0.250" (6.35mm) Through Hole; Manufacturer: Wurth Electronics; Current_A: 32A; Conn Gender: Female; Row_Count: 1; ContactFinish: Zinc; SizeZ_mm: 21.6mm; Max Wire Gauge: 10; Min Wire Gauge: 30; Voltage_V: 450V; AEC Qualified: No; Is Female: yes
J5 = CMP-0086764-1: 2 Position Wire to Board Terminal Block Horizontal with Board 0.400" (10.16mm) Through Hole; Manufacturer: Wurth; Current_A: 57A; Voltage_V: 750V; ContactFinish: Zinc; Row_Count: 1
J10-J12 = CMP-0096350-1: 2 Position Wire to Board Terminal Block Horizontal with Board 0.197" (5.00mm) Through Hole; Manufacturer: Wurth Electronics; Row_Count: 1; AEC Qualified: No; DUT-Pitch_mm: 5mm; Max Wire Gauge: 12; Is Female: yes; ContactFinish: Tin,Nickel; Min Wire Gauge: 30; Current_A: 14A; Voltage_V: 300V; SizeZ_mm: 13.9mm; Conn Gender: Female
J23 = CMP-0075407-2: as J13 on sheet MD133_TCAN284x
L1 = CMP-0087162-1: FIXED IND 2.2UH 16A 2.2 MOHM; Manufacturer: Wurth Electronics; Material: Composite; Isat: 34A; DCR_ohm: 2.42m; SizeZ_mm: 9.1mm; AEC Qualified: No; Symbol Name: SYM-74439369022
Q1 = CMP-0000375-2: Transistor, NPN, 65 V, 0.1 A, SOT-23; Manufacturer: ON Semiconductor; CompType: BJT; PNP: 0; NPN: 1; Vceo_V: 65V; Vcesat1_V: 700mV; Value: 65 V; IcRated_A: 100mA; Value1: 0.1 A; HfeMax: 450; TaMin_C: -55°C; TaMax_C: 150°C; U/M: EA; AEC Category: Q101; SizeArea_mm2: 7.5; SizeAreaWB_mm2: 14; SizeX_mm: 2.5; SizeY_mm: 3; SizeZ_mm: 1.1
Q2-Q6 Q8 = CMP-0000713-2: MOSFET, N-CH, 40 V, 100 A, DNK0008A (VSON-CLIP-8); Alternate Manufacturer: None; Manufacturer: Texas Instruments; SizeZ_mm: 1; ChType: N; Value2: 37 nC; Value1: 0.002; VdsMax_V: 40V; SizeX_mm: 6; SizeY_mm: 5; Vgs_V: 20V; Value: 40V; Rdson45_ohm: 2.3m; SizeArea_mm2: 30; AEC Category: Q101; IdsMax_A: 100A; SizeAreaWB_mm2: 56; U/M: EA; QgTyp_nC: 37
Q7 = CMP-0000594-1: MOSFET, N-CH, 30 V, 25 A, DQJ0008A (VSONP-8); Alternate Manufacturer: None; Manufacturer: Texas Instruments; SizeZ_mm: 1.1; ChType: N; Value2: 11.6 nC; Value1: 0.013; VdsMax_V: 30V; SizeX_mm: 6; SizeAreaWB_mm2: 55.2; SizeY_mm: 4.9; Vgs_V: 20V; QgTyp_nC: 11.6; Value: 30V; Rdson45_ohm: 13.3m; SizeArea_mm2: 29.4; AEC Category: Q101; IdsMax_A: 25A; U/M: EA
R32 R33 = CMP-0025886-5: as R67 on sheet MD133_TCAN284x
R34 R35 R37-R42 R45 R53 = CMP-0025885-5: as R64 on sheet MD133_TCAN284x
R36 = CMP-0086254-1: RES, 0.007, 1%, 7 W, AEC-Q200 Grade 0, 7.1x4.6mm; Manufacturer: Vishay-Dale; Res_ohm: 7m; EIA_Code: E96; Power_W: 7W; SizeArea_mm2: 32.2; SizeAreaWB_mm2: 59.4; SizeY_mm: 4.6; Value_Code: 7L000; AEC Category: Q200; SizeX_mm: 7; TempCo: 75 ppm/C; Value: 0.007; AEC Grade: 0; AEC Qualified: Y; SizeZ_mm: 1.75
R47 = CMP-0025899-5: as R65 on sheet MD133_TCAN284x
R51 = CMP-0022918-5: RES, 220, 1%, 0.1 W, 0603; Manufacturer: Yageo; Power_W: 100mW; TempCo: 100 ppm/C; Value_Code: 220R; Value: 220; SizeX_mm: 1.6; SizeY_mm: 0.8; SizeZ_mm: 1; Value2: 0.1W; SizeArea_mm2: 1.28; AEC Qualified: N; VDC_V: 75V; AEC Category: Q200; SizeAreaWB_mm2: 4.68
R52 R58 = CMP-0025885-5: RES, 0, 5%, 0.1 W, 0603; Manufacturer: Yageo; Power_W: 100mW; Res_ohm: 0; SizeZ_mm: 1; Value: 0; AEC Qualified: N; VDC_V: 75V; AEC Category: Q200; EIA_Code: E24; SizeArea_mm2: 1.28; SizeAreaWB_mm2: 4.68; SizeX_mm: 1.6; SizeY_mm: 0.8; TempCo: 200 ppm/C; Value2: 0.1W; Value_Code: 0000
R57 = CMP-0022895-5: RES, 1.00 k, 1%, 0.1 W, 0603; Manufacturer: Yageo; Power_W: 100mW; TempCo: 100 ppm/C; Value_Code: 1k00; Value: 1.00k; EIA_Code: E96; Res_ohm: 1k; SizeX_mm: 1.6; SizeY_mm: 0.8; SizeZ_mm: 1; Value2: 0.1W; SizeArea_mm2: 1.28; AEC Qualified: N; VDC_V: 75V; AEC Category: Q200; SizeAreaWB_mm2: 4.68
R66 R75 = CMP-0078790-1: RES, 0, 0.05%, 2 W, AEC-Q200 Grade 0, 2512; Manufacturer: Stackpole Electronics Inc; AEC Qualified: Y; AEC Category: Q200; Value: 0; Power_W: 2W
SH1 SH2 = CMP-0075110-1: 1mm Uninsulated Shorting Plug, 10.16mm spacing, TH; PartNumber: D3082-05; Manufacturer: Harwin; CNHeader: False; CompType: Jumper Wire; Green_Lifecycle: Active; Green_REACh: Passed
SH-J21 = CMP-0003761-2: Shunt, 2.54mm, Gold, Black; Manufacturer: Wurth Elektronik
TP20 TP21 = CMP-0055147-2: Test Point, Multipurpose, Red, TH; Manufacturer: Keystone Electronics; CNHeader: FALSE; Green_Lifecycle: Active; Green_REACh: Passed; ContactFinish: Silver; CT: TRUE
TP22-TP24 TP27-TP29 TP31-TP42 TP44 TP46-TP48 = CMP-0055149-2: Test Point, Multipurpose, White, TH; Manufacturer: Keystone Electronics; ContactFinish: Silver; CT: TRUE; CNHeader: FALSE; Green_Lifecycle: Active; Green_REACh: Passed
TP25 TP26 = CMP-0055148-2: Test Point, Multipurpose, Black, TH; Manufacturer: Keystone Electronics; CNHeader: FALSE; Green_Lifecycle: Active; Green_REACh: Passed; ContactFinish: Silver; CT: TRUE
TP30 TP43 TP45 = CMP-0003719-1: Testpoint; Manufacturer: Texas Instruments; CompType: Pad
U2 = CMP-0128166-1: Manufacturer: Texas Instruments; SizeZ_mm: 1mm; Standoff Height: 0mm

## Sheet Sheet1.SchDoc
size A
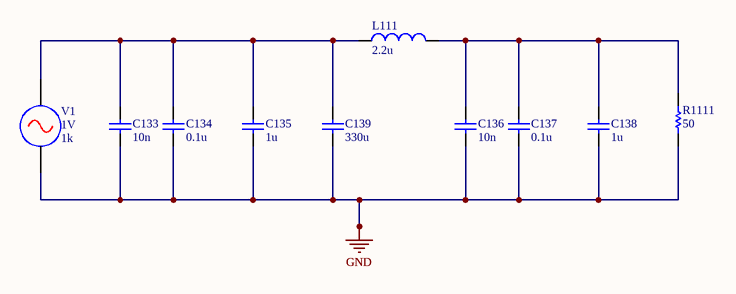
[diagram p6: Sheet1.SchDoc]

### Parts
C133  value 10n  (hidden comment: Capacitor)
C134  value 0.1u  (hidden comment: Capacitor)
C135  value 1u  (hidden comment: Capacitor)
C136  value 10n  (hidden comment: Capacitor)
C137  value 0.1u  (hidden comment: Capacitor)
C138  value 1u  (hidden comment: Capacitor)
C139  value 330u  (hidden comment: Capacitor)
L111  value 2.2u  (hidden comment: Inductor)
R1111  value 50  (hidden comment: Resistor)
V1  Amp: 1V  Freq: 1k  (hidden comment: AC Voltage Source)

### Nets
GND: C133.1 C134.1 C135.1 C136.1 C137.1 C138.1 C139.1 R1111.1 V1.2
NetC133_2: C133.2 C134.2 C135.2 C139.2 L111.1 V1.1
NetC136_2: C136.2 C137.2 C138.2 L111.2 R1111.2

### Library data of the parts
C133-C139 = Capacitor: SimulationGenericComponent: True
L111 = Inductor: SimulationGenericComponent: True
R1111 = Resistor: TC1: 0; SimulationGenericComponent: True
V1 = AC Voltage Source: SimulationGenericComponent: True; DC: 0

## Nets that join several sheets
3V3: MD133_XDS110 (J1.4), MD133_M0 (R22.1)
DVDD: MD133_M0 (J2.24), MD133_DRV800x (C43.2 U2.24)
GND: MD133_XDS110 (44 pins), MD133_M0 (18 pins), MD133_TCAN284x (29 pins), MD133_DRV800x (70 pins), Sheet1 (9 pins)
PVDD: MD133_M0 (D10.2 R76.2), MD133_TCAN284x (R64.2), MD133_DRV800x (32 pins)
VCC1: MD133_M0 (R21.2), MD133_TCAN284x (7 pins)
BSL_INVOKE: MD133_XDS110 (XDS1.42), MD133_M0 (R23.2 TP8.1)
CAN_RX: MD133_M0 (U1.6), MD133_TCAN284x (U3.24)
CAN_TX: MD133_M0 (U1.5), MD133_TCAN284x (U3.23)
DRVOFF: MD133_M0 (J2.20 TP18.1), MD133_DRV800x (U2.22)
GD_IN1: MD133_M0 (J2.2 TP9.1), MD133_DRV800x (U2.13)
GD_IN2: MD133_M0 (J2.4 TP10.1), MD133_DRV800x (U2.14)
IPROPI/PWM2: MD133_M0 (J2.16 J3.1 TP16.1), MD133_DRV800x (C67.1 C68.1 R57.2 U2.20)
MCU_CAN_GFO: MD133_M0 (U1.1), MD133_TCAN284x (U3.25)
MCU_CAN_LRXD: MD133_M0 (U1.57), MD133_TCAN284x (U3.22)
MCU_CAN_LTXD: MD133_M0 (U1.56), MD133_TCAN284x (U3.21)
MCU_CAN_nINT: MD133_M0 (U1.4), MD133_TCAN284x (U3.15)
MCU_CAN_nRST: MD133_M0 (U1.14), MD133_TCAN284x (U3.14)
MCU_CAN_SW: MD133_M0 (U1.3), MD133_TCAN284x (J20.2 U3.16)
MCU_nSCS_CAN: MD133_M0 (TP49.1 U1.29), MD133_TCAN284x (U3.20)
MCU_SCLK: MD133_M0 (J2.13 U1.61), MD133_TCAN284x (U3.17)
MCU_SDI: MD133_M0 (J2.9 U1.60), MD133_TCAN284x (U3.18)
MCU_SDO: MD133_M0 (J2.11 U1.59), MD133_TCAN284x (U3.19)
nSCS_DRV: MD133_M0 (J2.8 TP12.1), MD133_DRV800x (U2.16)
nSLEEP: MD133_M0 (J2.22 TP19.1), MD133_DRV800x (U2.23)
PWM1: MD133_M0 (J2.6 TP11.1), MD133_DRV800x (U2.15)
RST: MD133_XDS110 (J1.10), MD133_M0 (5 pins)
SCLK: MD133_M0 (J2.14 TP15.1), MD133_DRV800x (U2.19)
SDI: MD133_M0 (J2.10 TP13.1), MD133_DRV800x (U2.17)
SDO: MD133_M0 (J2.12 TP14.1), MD133_DRV800x (U2.18)
SO: MD133_M0 (J2.18 TP17.1), MD133_DRV800x (C63.1 R53.1)
SWCLK: MD133_XDS110 (J1.14), MD133_M0 (U1.13)
SWDIO: MD133_XDS110 (J1.12), MD133_M0 (U1.12)
UART1_RX: MD133_XDS110 (J1.6), MD133_M0 (U1.53)
UART1_TX: MD133_XDS110 (J1.8), MD133_M0 (U1.52)
WAKE1: MD133_M0 (U1.22), MD133_TCAN284x (J13.3 R43.1 U3.2)
WAKE2: MD133_M0 (U1.21), MD133_TCAN284x (J13.2 R73.1 U3.1)
WAKE3: MD133_M0 (U1.20), MD133_TCAN284x (J13.1 R74.1 U3.32)

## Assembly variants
001: not fitted C40 C41 C42 C49 C50 C51 C52 C53 C54 C55 C56 C57 C59 C60 C61 C62 C64 C65 C66 C68 C71 C72 C73 C87 C88 C89 C90 C91 C92 D11 J21 L1 L2 R21 U3 Y2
